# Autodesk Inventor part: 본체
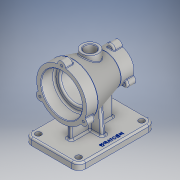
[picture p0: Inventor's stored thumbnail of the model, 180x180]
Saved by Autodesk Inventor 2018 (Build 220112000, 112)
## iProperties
Created: 2020-03
Part Number: 본체
Material: 알루미늄 6061
Document SubType Name: Modeling
Designer: Administrator
Density: 2.7 g/cm^3
Appearance: 알루미늄 - 평지
Mass: 999.489 g
Surface Area: 863.413 cm^2
Volume: 370.181 cm^3
Author: Administrator
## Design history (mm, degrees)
sketch "스케치1"
  geometry: L1 (0, 0)-(0, 44); L2 (0, 44)-(-20, 44); L3 (-20, 44)-(-82.164, 27.5); L4 (-82.164, 27.5)-(-100, 27.5); L5 (-100, 27.5)-(-100, 0); L6 (-100, 0)-(0, 0)
  constraints: 12 end point, 3 perpendicular, 1 parallel, 1 vertical
  dimensions: "d0" = 20 distance from line of L2.end L1; "d1" = 100 distance between parallel lines of L5 L1; "d2" = 88 diameter of L2 L6; "d3" = 55 diameter of L4 L6
revolve "회전1" sketch "스케치1" stored, may be unused: angle "d4" = 90 deg
sketch "스케치2"
  geometry: L1 (0, 0)-(23, 0); L2 (23, 0)-(23, 36); L3 (23, 36)-(0, 36); L4 (0, 36)-(0, 0); L5 (23, 0)-(70, 0); L6 (70, 0)-(70, 26); L7 (70, 26)-(23, 26); L8 (23, 26)-(23, 0); L9 (100, 27.5)-(100, -27.5) reference; L10 (70, 0)-(100, 0); L11 (100, 0)-(100, 20); L12 (100, 20)-(70, 20); L13 (70, 20)-(70, 0)
  constraints: 24 end point, 6 parallel, 3 horizontal, 3 perpendicular, 1 point on line
  dimensions: "d5" = 23 distance of L2.end L3.end; "d6" = 30 distance of L11.end L12.end; "d7" = 72 diameter of L3 L1; "d8" = 52 diameter of L7 L5; "d9" = 40 diameter of L12 L10
revolve "회전2" sketch "스케치2" stored, may be unused: angle "d10" = 90 deg
chamfer "모따기1" distance "d11" = 1; stored, may be unused: second distance "d12" = 2, angle "d13" = 45 deg
fillet "모깎기1" dims "d14" = 3
fillet "모깎기2" dims "d15" = 3
node "작업 평면1"
sketch "스케치3"
  geometry: L1 (0, -44)-(0, 44) reference; L2 (-100, -27.5)-(-100, 27.5) reference; L3 (0, 0)-(-100, 0); L4 (17.5, 47.5)-(-117.5, 47.5); L5 (-117.5, 47.5)-(-117.5, -47.5); L6 (-117.5, -47.5)-(17.5, -47.5); L7 (17.5, -47.5)-(17.5, 47.5); L8 (17.5, 47.5)-(-117.5, -47.5); L9 (-117.5, 47.5)-(17.5, -47.5); 2 further points
  constraints: 14 end point, 6 midpoint, 2 parallel, 1 horizontal, 1 perpendicular
  dimensions: "d17" = 135 distance of L5.end L6.end; "d18" = 95 distance of L4.end L5.end
extrude "돌출1" join sketch "스케치3" distance "d19" = 12; taper "d20" = 0 deg
sketch "스케치4"
  geometry: L1 (117.5, 47.5)-(-17.5, 47.5) reference; L2 (-17.5, 47.5)-(-17.5, -47.5) reference; L3 (-17.5, -47.5)-(117.5, -47.5) reference; L4 (-17.5, 47.5)-(-17.5, -47.5) reference; L5 (117.5, 47.5)-(-17.5, 47.5) reference; L6 (117.5, -47.5)-(117.5, 47.5) reference; L7 (13, -4)-(87, -4); L8 (87, -4)-(87, 4); L9 (87, 4)-(13, 4); L10 (13, 4)-(13, -4); L11 (13, -4)-(87, 4); L12 (87, -4)-(13, 4); 3 further points
  constraints: 12 end point, 3 midpoint, 2 parallel, 1 horizontal, 1 horizontal alignment, 1 perpendicular
  dimensions: "d21" = 67.5 distance from line of point (50, 0) L6; "d22" = 8 distance of L7.end L8.end; "d23" = 74 distance of L8.end L9.end
extrude "돌출2" join sketch "스케치4" stored distance "d24" = 12; taper "d25" = 0 deg
node "작업 평면2"
feature "리브1" dims "d28" = 1, "d29" = 8, "d30" = 0, "d31" = 0, "d32" = 1, "d33" = 1
node "작업 평면3"
sketch "스케치6"
  geometry: L1 (17.5, -47.5)-(17.5, 47.5) reference; L2 (17.5, 0)-(-117.5, 0); L3 (-117.5, 47.5)-(-117.5, -47.5) reference; C1 r 15 at (-50, 0); 1 further point
  constraints: 3 midpoint, 2 end point, 1 centre point
  dimensions: "d35" = 30 diameter of C1
extrude "돌출3" join sketch "스케치6" stored distance "d36" = 12; taper "d37" = 0 deg
sketch "스케치7"
  geometry: C1 r 15 at (0, 0) reference; C2 r 10 at (0, 0); 1 further point
  constraints: 1 centre point, 1 coincident
  dimensions: "d38" = 20 diameter of C2
extrude "돌출4" cut sketch "스케치7" stored distance "d39" = 12; taper "d40" = 0 deg; dims "d17" = 135, "d18" = 95, "d154" = 3
chamfer "모따기2" distance "d41" = 1; stored, may be unused: second distance "d42" = 2, angle "d43" = 45 deg
fillet "모깎기3" dims "d44" = 12
fillet "모깎기4" dims "d45" = 3
fillet "모깎기5" dims "d46" = 3
fillet "모깎기6" dims "d47" = 3
fillet "모깎기7" dims "d48" = 3
fillet "모깎기8" dims "d49" = 3
fillet "모깎기9" dims "d50" = 3
fillet "모깎기10" dims "d51" = 3
fillet "모깎기11" dims "d52" = 3
fillet "모깎기12" dims "d53" = 3
sketch "스케치8"
  geometry: A1 r 12 centre (105.5, 35.5) between (117.5, 35.5) and (105.5, 47.5) reference; A2 r 12 centre (105.5, -35.5) between (105.5, -47.5) and (117.5, -35.5) reference; A3 r 12 centre (-5.5, -35.5) between (-17.5, -35.5) and (-5.5, -47.5) reference; A4 r 12 centre (-5.5, 35.5) between (-5.5, 47.5) and (-17.5, 35.5) reference; 5 further points
  constraints: 4 coincident
hole "구멍1" sketch "스케치8" at (105.5, 35.5), (105.5, -35.5), (-5.5, -35.5), (-5.5, 35.5) diameter "d54" = 10; stored, may be unused: countersink angle "d58" = 90 deg, drill point angle "d60" = 118 deg; dims "d55" = 6, "d56" = 4, "d57" = 2, "d59" = 8
sketch "스케치9"
  geometry: C1 r 44 at (0, 0); A1 r 43.9 centre (0, 0) between (6.566, -43.406) and (-6.566, -43.406) reference; A2 r 7 centre (0, 43.9) between (6.978, 43.342) and (-6.978, 43.342); 2 further points
  constraints: 6 point on circle, 2 centre point, 1 coincident, 1 vertical alignment
  dimensions: "d61" = 88 diameter of C1; "d62" = 14 diameter of A2
extrude "돌출5" join sketch "스케치9" distance "d63" = 15; taper "d64" = 0 deg
sketch "스케치10"
  geometry: A1 r 7 centre (0, 0) between (6.985, -0.458) and (-6.985, -0.458) reference; 2 further points
  constraints: 1 coincident
hole "구멍2" sketch "스케치10" at (0, 0) diameter "d68" = 4.134; stored, may be unused: countersink angle "d72" = 90 deg, drill point angle "d74" = 118 deg; dims "d69" = 9, "d70" = 4, "d71" = 2, "d73" = 11
fillet "모깎기13" dims "d78" = 1
sketch "스케치11"
  geometry: A1 r 27.5 centre (0, 0) between (6.943, 26.609) and (-6.943, 26.609); A2 r 27.5 centre (0, 0) between (6.311, -26.766) and (-6.311, -26.766) reference; A3 r 7 centre (0, 27.5) between (6.943, 26.609) and (-6.943, 26.609); 1 further point
  constraints: 6 point on circle, 2 centre point, 1 coincident
  dimensions: "d81" = 7 radius of A3
extrude "돌출6" join sketch "스케치11" distance "d82" = 15; taper "d83" = 0 deg
sketch "스케치12"
  geometry: A1 r 7 centre (0, 0) between (6.943, -0.891) and (-6.943, -0.891) reference; 2 further points
  constraints: 1 coincident
hole "구멍3" sketch "스케치12" at (0, 0) diameter "d87" = 4.134; stored, may be unused: countersink angle "d91" = 90 deg, drill point angle "d93" = 118 deg; dims "d88" = 9, "d89" = 4, "d90" = 2, "d92" = 11
fillet "모깎기14" dims "d97" = 3
fillet "모깎기15" dims "d98" = 3
fillet "모깎기16" dims "d99" = 1
sketch "스케치13"
  geometry: L1 (-17.5, 35.5)-(-17.5, -35.5) reference; L2 (-17.5, 0)-(118.541, 0); L3 (-5.5, -47.5)-(105.5, -47.5) reference; 3 further points
  constraints: 2 end point, 2 midpoint, 1 horizontal, 1 vertical alignment, 1 other
  dimensions: "d100" = 10 distance from line of point (50.521, -37.5) L3
feature "엠보싱1" sketch "스케치13" dims "d5" = 23, "d6" = 30, "d7" = 72, "d8" = 52, "d9" = 40, "d101" = 0.5, "d102" = 0
sketch "스케치14"
  geometry: 1 further point
sketch "스케치15"
  geometry: 1 further point
sketch "스케치16"
  geometry: L1 (0, 0)-(0, 44); L2 (0, 44)-(20, 44); L3 (20, 44)-(77, 27.5); L4 (77, 27.5)-(100, 27.5); L5 (100, 27.5)-(100, 0); L6 (100, 0)-(0, 0)
  constraints: 12 end point, 3 perpendicular, 1 parallel, 1 vertical
  dimensions: "d103" = 20 distance of L1.end L2.end; "d104" = 100 distance between parallel lines of L5 L1; "d105" = 77 distance from line of L3.end L1; "d106" = 88 diameter of L2 L6; "d107" = 55 diameter of L4 L6
revolve "회전3" sketch "스케치16" stored, may be unused: angle "d108" = 90 deg
sketch "스케치17"
  geometry: L1 (13, -4)-(87, -4); L2 (87, -4)-(87, 4); L3 (87, 4)-(13, 4); L4 (13, 4)-(13, -4); L5 (13, -4)-(87, 4); L6 (87, -4)-(13, 4); L7 (117.5, -35.5)-(117.5, 35.5) reference; 3 further points
  constraints: 12 end point, 3 midpoint, 2 parallel, 1 horizontal, 1 horizontal alignment, 1 perpendicular
  dimensions: "d109" = 67.5 distance from line of point (50, 0) L7; "d110" = 74 distance of L2.end L3.end; "d111" = 8 distance of L1.end L2.end
extrude "돌출7" join sketch "스케치17" stored distance "d112" = 10; taper "d113" = 0 deg
node "작업 평면4"
sketch "스케치18"
  geometry: L1 (71.029, 12.5)-(71.029, 12) reference; L2 (71.029, 12)-(80, 12) reference; L3 (83, 9)-(83, 0) reference; L4 (83, 0)-(-12, 0) reference; L5 (-12, 0)-(-12, 9) reference; L6 (-9, 12)-(31.5, 12) reference; L7 (31.5, 12)-(31.5, 51.911) reference; L8 (39.5, 51.911)-(39.5, 12) reference; L9 (39.5, 12)-(70.615, 12) reference; L10 (70.615, 12)-(70.615, 12.5) reference; L11 (70.615, 12.5)-(71.029, 12.5) reference; L12 (0, 12)-(71, 12) reference; L13 (60.5, 12)-(56.427, 58.553); L14 (71, 0)-(0, 0) reference; L15 (35.5, 0)-(35.5, 87); A1 r 3 centre (80, 9) between (83, 9) and (80, 12) reference; A2 r 3 centre (-9, 9) between (-9, 12) and (-12, 9) reference; A3 r 35.316 centre (35.5, 87) between (39.5, 51.911) and (31.5, 51.911) reference; 1 further point
  constraints: 4 end point, 1 midpoint, 1 point on circle, 1 point on line, 1 vertical
  dimensions: "d114" = 25 distance from line of L13.start L15; "d115" = 95 deg angle of L13 L9
feature "리브2" sketch "스케치18" dims "d116" = 1, "d117" = 8, "d118" = 0, "d119" = 0, "d120" = 1, "d121" = 1
sketch "스케치19"
  geometry: L1 (0, 0)-(23, 0); L2 (23, 0)-(23, 36); L3 (23, 36)-(0, 36); L4 (0, 36)-(0, 0); L5 (23, 0)-(70, 0); L6 (70, 26)-(23, 26); L7 (23, 26)-(23, 0); L8 (70, 26)-(70, 0); L9 (100, -27.5)-(100, 27.5) reference; L10 (70, 0)-(100, 0); L11 (100, 0)-(100, 20); L12 (100, 20)-(70, 20); L13 (70, 20)-(70, 0)
  constraints: 24 end point, 5 parallel, 3 horizontal, 2 perpendicular, 1 point on line, 1 vertical
  dimensions: "d122" = 23 distance of L2.end L3.end; "d124" = 72 diameter of L3 L1; "d125" = 52 diameter of L6 L5; "d126" = 30 distance of L11.end L12.end; "d127" = 40 diameter of L12 L10
revolve "회전4" sketch "스케치19" stored, may be unused: angle "d128" = 90 deg
node "작업 평면5"
sketch "스케치20"
  geometry: L1 (0, 0)-(-100, 0); L2 (-100, 27.5)-(-100, -27.5) reference; C1 r 15 at (-50, 0)
  constraints: 2 end point, 2 midpoint, 1 centre point
  dimensions: "d130" = 30 diameter of C1
extrude "돌출8" join sketch "스케치20" stored distance "d131" = 10; taper "d132" = 0 deg
sketch "스케치21"
  geometry: C1 r 15 at (0, 0) reference; C2 r 10 at (0, 0); 1 further point
  constraints: 1 centre point, 1 coincident
  dimensions: "d133" = 20 diameter of C2
extrude "돌출9" cut sketch "스케치21" stored distance "d134" = 10; taper "d135" = 0 deg
sketch "스케치22"
  geometry: C1 r 7 at (0, 44); A1 r 44 centre (0, 0) between (-4, -43.818) and (4, -43.818); A2 r 44 centre (0, 0) between (4, -43.818) and (-4, -43.818) reference; 1 further point
  constraints: 2 centre point, 1 coincident, 1 point on circle
  dimensions: "d136" = 88 diameter of A1; "d137" = 14 diameter of C1
extrude "돌출10" join sketch "스케치22" distance "d138" = 15; taper "d139" = 0 deg
sketch "스케치23"
  geometry: C1 r 7 at (0, 27.5); 2 further points
  constraints: 2 vertical alignment, 1 centre point, 1 other
  dimensions: "d143" = 14 diameter of C1
extrude "돌출11" join sketch "스케치23" distance "d144" = 15; taper "d145" = 0 deg
chamfer "모따기3" distance "d149" = 1; stored, may be unused: second distance "d150" = 2, angle "d151" = 45 deg
fillet "모깎기17" dims "d152" = 3
fillet "모깎기18" dims "d153" = 1
fillet "모깎기19" dims "d154" = 3
fillet "모깎기20" dims "d155" = 3
fillet "모깎기21" dims "d156" = 3
fillet "모깎기22" dims "d157" = 3
fillet "모깎기23" dims "d158" = 3
fillet "모깎기24" dims "d159" = 3
fillet "모깎기25" dims "d160" = 3
fillet "모깎기26" dims "d161" = 3
fillet "모깎기27" dims "d162" = 3
sketch "스케치24"
  geometry: 2 further points
hole "구멍4" sketch "스케치24" at (0, 0) diameter "d163" = 4.134; stored, may be unused: countersink angle "d167" = 90 deg, drill point angle "d169" = 118 deg; dims "d164" = 9, "d165" = 4, "d166" = 2, "d168" = 11
sketch "스케치25"
  geometry: A1 r 7 centre (0, 0) between (6.943, -0.891) and (-6.943, -0.891) reference; 2 further points
  constraints: 1 coincident
hole "구멍5" sketch "스케치25" at (0, 0) diameter "d173" = 4.134; stored, may be unused: countersink angle "d177" = 90 deg, drill point angle "d179" = 118 deg; dims "d174" = 9, "d175" = 4, "d176" = 2, "d178" = 11
fillet "모깎기28" dims "d183" = 3
fillet "모깎기29" dims "d184" = 3
fillet "모깎기30" dims "d185" = 1
node "솔리드1"
mirror "미러1"
pattern_circular "원형 패턴1" dims angle "d66" = 360 deg
pattern_circular "원형 패턴2" dims angle "d76" = 360 deg
pattern_circular "원형 패턴3" dims angle "d85" = 360 deg
pattern_circular "원형 패턴4" dims angle "d95" = 360 deg
mirror "미러2"
pattern_circular "원형 패턴5" dims angle "d141" = 360 deg
pattern_circular "원형 패턴6" dims angle "d147" = 360 deg
pattern_circular "원형 패턴7" dims angle "d171" = 360 deg
pattern_circular "원형 패턴8" dims angle "d181" = 360 deg
node "투영된 루프1"
sketch "스케치5"
  geometry: L1 (95, 12)-(95, 0) reference; L2 (95, 0)-(0, 0) reference; L3 (0, 0)-(0, 12) reference; L4 (0, 12)-(95, 12) reference; L5 (95, 12)-(0, 12) reference; L6 (72.5, 12)-(68.501, 57.714); L7 (95, 0)-(0, 0) reference; L8 (47.5, 0)-(47.5, 61); 2 further points
  constraints: 4 end point, 1 midpoint, 1 point on line, 1 vertical, 1 vertical alignment, 1 other
  dimensions: "d26" = 25 horizontal distance of L6.start L8.start
node "투영된 루프2"
node "절단 모서리 투영1"
node "절단 모서리 투영2"
other parameters: "d16" = -87, "d34" = 45, "d129" = 45
